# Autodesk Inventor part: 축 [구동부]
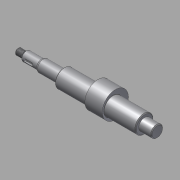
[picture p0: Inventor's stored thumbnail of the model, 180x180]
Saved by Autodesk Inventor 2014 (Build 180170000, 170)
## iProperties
Created: 2015-12
Part Number: 축 [구동부]
Document SubType Name: Modeling
Designer: mdu
Density: 1 g/cm^3
Material: 강철, 연강
Appearance: 강철
Mass: 62.304 g
Surface Area: 127.382 cm^2
Volume: 62.304 cm^3
Author: mdu
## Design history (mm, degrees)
sketch "스케치1"
  geometry: L1 (62, 100.9)-(62, 67.1) reference; L2 (51, 101.2)-(51, 84) reference; L3 (-51, 84)-(-51, 101.2) reference; L4 (-62, 67.1)-(-62, 100.9) reference; L5 (-51.6, 91.5)-(-61.4, 91.5) reference; L6 (51.6, 91.5)-(61.4, 91.5) reference; L7 (67, 84)-(-109, 84); L8 (-77, 64.201)-(-77, 103.799) reference; L9 (67, 84)-(67, 91.5); L10 (67, 91.5)-(51, 91.5); L11 (51, 91.5)-(51, 95.5); L12 (51, 95.5)-(-51, 95.5); L13 (-51, 95.5)-(-51, 91.5); L14 (-51, 91.5)-(-79, 91.5); L15 (-79, 91.5)-(-79, 90); L16 (-79, 90)-(-99, 90); L17 (-99, 90)-(-99, 87); L18 (-100.5, 88)-(-109, 88); L19 (-109, 88)-(-109, 84); L20 (-99, 87)-(-100.5, 87); L21 (-100.5, 87)-(-100.5, 88); 2 further points
  constraints: 32 end point, 7 parallel, 6 point on line, 5 perpendicular, 2 collinear, 2 horizontal, 1 midpoint, 4 other
  dimensions: "d0" = 5 distance from line of L7.start L1; "d2" = 2 distance between parallel lines of L15 L8; "d3" = 23 diameter of L12 L7; "d4" = 12 diameter of L16 L7; "d5" = 1.5 distance of L17.end L20.end; "d6" = 6 diameter of L20 L7; "d7" = 20 distance of L15.end L16.end; "d8" = 10 distance between parallel lines of L17 L19; "d9" = 8 diameter of L18 L7
revolve "회전1" sketch "스케치1" stored, may be unused: angle "d10" = 90 deg
sketch "스케치2"
  geometry: C1 r 11.5 at (84, 0) reference; C2 r 11.5 at (84, 0) reference; C3 r 16.5 at (87, 0); 1 further point
  constraints: 1 centre point, 1 horizontal alignment
  dimensions: "d11" = 33 diameter of C3; "d12" = 3 distance of C3.centre C1.centre
extrude "돌출1" join sketch "스케치2" stored distance "d13" = 22; taper "d14" = 0 deg
chamfer "모따기1" distance "d15" = 1; stored, may be unused: second distance "d16" = 2, angle "d17" = 45 deg
feature "스레드1" dims "d18" = 10, "d19" = 0
node "작업 평면1"
sketch "스케치3"
  geometry: L1 (-5, -2)-(3, -2); L2 (3, 2)-(-5, 2); L3 (-10, -5)-(-10, 5) reference; A1 r 2 centre (3, 0) between (3, -2) and (3, 2); A2 r 2 centre (-5, 0) between (-5, 2) and (-5, -2); 2 further points
  constraints: 4 end point, 4 point on circle, 4 tangent, 2 centre point, 1 horizontal, 1 horizontal alignment, 1 midpoint, 1 parallel
  dimensions: "d20" = 4 distance between parallel lines of L1 L2; "d21" = 12 dimension on A1 A2; "d22" = 3 distance edge to line of A2 L3
extrude "돌출2" cut sketch "스케치3" distance "d23" = 2.5; taper "d24" = 0 deg
fillet "모깎기1" dims "d25" = 0.3
fillet "모깎기2" dims "d26" = 3
node "솔리드1"
node "참조1"
node "참조2"
node "참조3"
node "참조4"
node "참조5"
node "투영된 루프1"
